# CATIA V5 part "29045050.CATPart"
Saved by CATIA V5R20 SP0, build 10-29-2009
Part number: 29045050
Definition: NONE
Nomenclature: 29045050
Source: Unknown
Description: 29045050
Bounding box of the stored display mesh (mm): x -25 to 44.548, y -36.5 to 71.048, z -26.5 to 26.5
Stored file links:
  C:\Users\Utente\Desktop\IO LAVORO\3D X SITO CF\X SITO\PLASTICA\RF1\29045050.CATPart
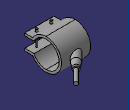
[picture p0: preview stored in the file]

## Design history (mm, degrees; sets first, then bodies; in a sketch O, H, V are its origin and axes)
Body1 "29045050" (main body)
  Solid1: solid without history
